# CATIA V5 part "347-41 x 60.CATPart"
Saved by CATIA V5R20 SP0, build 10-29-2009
Part number: 347-41 x 60
Definition: NONE
Nomenclature: 347-41 x 60
Source: Unknown
Description: 347-41 x 60
Bounding box of the stored display mesh (mm): x 0 to 60, y -27.5 to 27.5, z -27.5 to 27.5
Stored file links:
  C:\Users\Utente\Desktop\IO LAVORO\3D X SITO CF\X SITO\3D files 347\347-41 x 60.CATPart
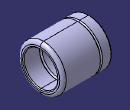
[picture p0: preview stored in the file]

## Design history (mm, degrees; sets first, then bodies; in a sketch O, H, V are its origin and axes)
Body1 "347-41 x 60" (main body)
  Solid1: solid without history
